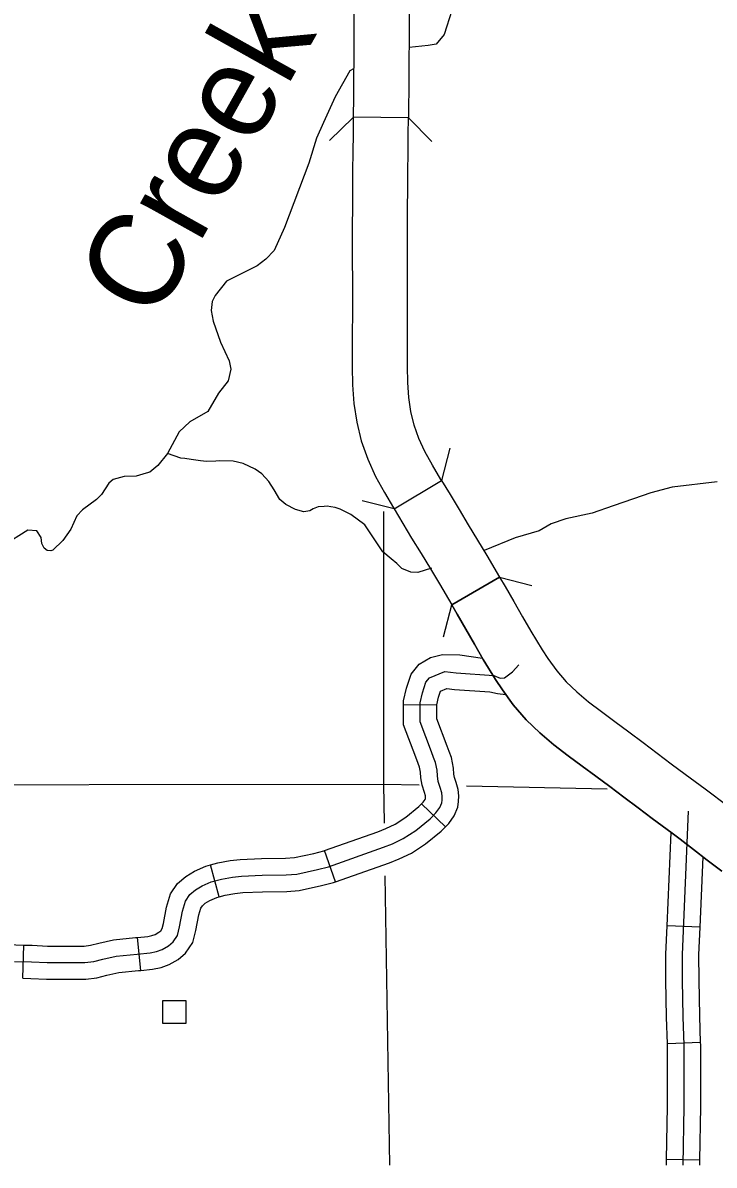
# Model space of a CAD drawing. Extents: x 1369885 to 1370219, y 379980 to 380218.
# Drawn here: x 1370041.37 to 1370053.81, y 380035.72 to 380056.29 of the extents above; entities that cross this region are included whole.
import ezdxf

# ---------------------------------------------------------------- set-up
doc = ezdxf.new("R2010")
doc.units = 0
for name, color, linetype in [('Level 10', 7, 'Continuous'), ('Level 32', 7, 'Continuous'), ('Level 35', 7, 'Continuous'), ('Level 37', 7, 'Continuous'), ('Level 5', 7, 'Continuous'), ('Level 56', 7, 'Continuous')]:
    doc.layers.add(name, color=color, linetype=linetype)

msp = doc.modelspace()

# ---------------------------------------------------------------- linework, layer by layer
at = {"layer": 'Level 10'}
for points in [[(1370047.332, 380056.674), (1370047.329, 380056.324), (1370047.326, 380055.979), (1370047.325, 380055.64), (1370047.321, 380055.305), (1370047.318, 380054.964), (1370047.316, 380054.593)], [(1370048.326, 380056.668), (1370048.323, 380056.316), (1370048.321, 380055.973), (1370048.319, 380055.632), (1370048.315, 380055.294), (1370048.31, 380054.582)], [(1370048.31, 380054.582), (1370047.316, 380054.593), (1370047.312, 380054.297), (1370047.308, 380053.964), (1370047.304, 380053.63), (1370047.301, 380053.298), (1370047.3, 380052.967), (1370047.298, 380052.639), (1370047.298, 380052.314), (1370047.299, 380051.993), (1370047.3, 380051.673), (1370047.3, 380051.353), (1370047.3, 380051.035), (1370047.299, 380050.721), (1370047.297, 380050.41), (1370047.298, 380050.096), (1370047.304, 380049.775), (1370047.327, 380049.441), (1370047.378, 380049.102), (1370047.459, 380048.763), (1370047.576, 380048.435), (1370047.718, 380048.126), (1370047.877, 380047.834), (1370048.043, 380047.559), (1370048.054, 380047.54), (1370048.906, 380048.053)], [(1370048.906, 380048.053), (1370048.895, 380048.072), (1370048.74, 380048.329), (1370048.607, 380048.573), (1370048.498, 380048.81), (1370048.414, 380049.047), (1370048.355, 380049.292), (1370048.316, 380049.548), (1370048.298, 380049.818), (1370048.293, 380050.107), (1370048.292, 380050.409), (1370048.293, 380050.717), (1370048.294, 380051.033), (1370048.294, 380051.353), (1370048.294, 380051.674), (1370048.294, 380051.995), (1370048.293, 380052.316), (1370048.293, 380052.637), (1370048.294, 380052.963), (1370048.296, 380053.29), (1370048.299, 380053.62), (1370048.302, 380053.952), (1370048.307, 380054.286), (1370048.31, 380054.582)], [(1370048.906, 380048.053), (1370049.058, 380047.8), (1370049.22, 380047.527), (1370049.386, 380047.253), (1370049.555, 380046.976), (1370049.722, 380046.701), (1370049.951, 380046.312)], [(1370048.054, 380047.54), (1370048.367, 380047.015), (1370048.537, 380046.737), (1370048.704, 380046.461), (1370048.868, 380046.19), (1370049.092, 380045.811)], [(1370049.951, 380046.312), (1370049.092, 380045.811), (1370049.188, 380045.646), (1370049.345, 380045.375), (1370049.499, 380045.105), (1370049.655, 380044.83), (1370049.879, 380044.465), (1370050.001, 380044.282), (1370050.197, 380044.008), (1370050.426, 380043.743), (1370050.674, 380043.504), (1370050.929, 380043.29), (1370051.185, 380043.093), (1370051.437, 380042.908), (1370051.684, 380042.726), (1370051.933, 380042.537), (1370052.186, 380042.346), (1370052.442, 380042.153), (1370052.696, 380041.965), (1370053.054, 380041.697), (1370053.199, 380041.59), (1370053.443, 380041.406), (1370053.688, 380041.215), (1370053.95, 380041.013)], [(1370053.95, 380041.013), (1370053.688, 380041.215), (1370053.443, 380041.406), (1370053.199, 380041.59), (1370053.054, 380041.697), (1370052.696, 380041.965), (1370052.442, 380042.153), (1370052.186, 380042.346), (1370051.933, 380042.537), (1370051.684, 380042.726), (1370051.437, 380042.908), (1370051.185, 380043.093), (1370050.929, 380043.29), (1370050.674, 380043.504), (1370050.426, 380043.743), (1370050.197, 380044.008), (1370050.001, 380044.282), (1370049.879, 380044.465), (1370049.655, 380044.83), (1370049.499, 380045.105), (1370049.345, 380045.375), (1370049.188, 380045.646), (1370049.092, 380045.811), (1370049.951, 380046.312)], [(1370049.951, 380046.312), (1370050.048, 380046.145), (1370050.207, 380045.871), (1370050.363, 380045.598), (1370050.512, 380045.336), (1370050.718, 380045.001), (1370050.82, 380044.847), (1370050.98, 380044.623), (1370051.149, 380044.427), (1370051.339, 380044.245), (1370051.553, 380044.065), (1370051.783, 380043.888), (1370052.027, 380043.709), (1370052.279, 380043.522), (1370052.533, 380043.331), (1370052.786, 380043.139), (1370053.037, 380042.95), (1370053.29, 380042.762), (1370053.648, 380042.495), (1370053.794, 380042.387), (1370054.048, 380042.195)], [(1370049.951, 380046.312), (1370050.048, 380046.145), (1370050.207, 380045.871), (1370050.363, 380045.598), (1370050.512, 380045.336), (1370050.718, 380045.001), (1370050.82, 380044.847), (1370050.98, 380044.623), (1370051.149, 380044.427), (1370051.339, 380044.245), (1370051.553, 380044.065), (1370051.783, 380043.888), (1370052.027, 380043.709), (1370052.279, 380043.522), (1370052.533, 380043.331), (1370052.786, 380043.139), (1370053.037, 380042.95), (1370053.29, 380042.762), (1370053.648, 380042.495), (1370053.794, 380042.387), (1370054.048, 380042.195)]]:
    msp.add_lwpolyline(points, dxfattribs=at)
at = {"layer": 'Level 32'}
for p, q in [((1370048.818, 380044.01), (1370048.222, 380044.007)), ((1370048.975, 380041.813), (1370048.547, 380042.229)), ((1370046.996, 380040.823), (1370046.798, 380041.385)), ((1370044.9, 380040.552), (1370044.745, 380041.128)), ((1370053.56, 380040.003), (1370052.964, 380040.029)), ((1370043.49, 380039.227), (1370043.433, 380039.821)), ((1370041.368, 380039.087), (1370041.385, 380039.684)), ((1370053.569, 380037.926), (1370052.973, 380037.906)), ((1370053.554, 380035.811), (1370052.957, 380035.821))]:
    msp.add_line(p, q, dxfattribs=at)
for points in [[(1370048.222, 380044.007), (1370048.221, 380044.08), (1370048.274, 380044.308), (1370048.358, 380044.563), (1370048.503, 380044.743), (1370048.704, 380044.862), (1370048.922, 380044.918), (1370049.234, 380044.91), (1370049.643, 380044.852)], [(1370041.218, 380039.39), (1370041.524, 380039.381), (1370041.803, 380039.368), (1370042.046, 380039.368), (1370042.261, 380039.368), (1370042.486, 380039.368), (1370042.644, 380039.386), (1370042.806, 380039.431), (1370043.049, 380039.485), (1370043.424, 380039.52), (1370043.658, 380039.543), (1370043.773, 380039.565), (1370043.874, 380039.603), (1370043.989, 380039.669), (1370044.072, 380039.741), (1370044.153, 380039.856), (1370044.189, 380040.009), (1370044.243, 380040.297), (1370044.297, 380040.477), (1370044.375, 380040.594), (1370044.476, 380040.679), (1370044.593, 380040.751), (1370044.76, 380040.823), (1370044.944, 380040.873), (1370045.142, 380040.909), (1370045.302, 380040.927), (1370045.675, 380040.942), (1370046.109, 380040.949), (1370046.298, 380040.963), (1370046.673, 380041.045), (1370046.87, 380041.095), (1370047.862, 380041.444), (1370048.023, 380041.508), (1370048.215, 380041.602), (1370048.44, 380041.748), (1370048.7, 380041.958), (1370048.805, 380042.066), (1370048.872, 380042.159), (1370048.91, 380042.247), (1370048.915, 380042.294), (1370048.918, 380042.358), (1370048.91, 380042.428), (1370048.883, 380042.522), (1370048.845, 380042.632), (1370048.831, 380042.729), (1370048.825, 380042.831), (1370048.799, 380042.974), (1370048.761, 380043.062), (1370048.726, 380043.167), (1370048.521, 380043.705), (1370048.52, 380044.047), (1370048.561, 380044.228), (1370048.625, 380044.418), (1370048.688, 380044.497), (1370048.963, 380044.612), (1370049.167, 380044.585), (1370049.844, 380044.54), (1370049.961, 380044.49), (1370050.036, 380044.495), (1370050.183, 380044.606), (1370050.298, 380044.733)], [(1370048.818, 380044.01), (1370048.818, 380044.013), (1370048.849, 380044.147), (1370048.885, 380044.256), (1370049.003, 380044.306), (1370049.137, 380044.288), (1370049.774, 380044.245), (1370049.913, 380044.216), (1370050.061, 380044.198)], [(1370048.547, 380042.229), (1370048.575, 380042.258), (1370048.611, 380042.307), (1370048.618, 380042.325), (1370048.619, 380042.346), (1370048.616, 380042.369), (1370048.598, 380042.433), (1370048.554, 380042.561), (1370048.534, 380042.698), (1370048.528, 380042.796), (1370048.511, 380042.887), (1370048.482, 380042.955), (1370048.445, 380043.067), (1370048.223, 380043.65), (1370048.222, 380044.007)], [(1370048.975, 380041.813), (1370049.034, 380041.874), (1370049.133, 380042.011), (1370049.2, 380042.168), (1370049.213, 380042.268), (1370049.218, 380042.37), (1370049.203, 380042.487), (1370049.168, 380042.61), (1370049.136, 380042.704), (1370049.128, 380042.76), (1370049.122, 380042.867), (1370049.086, 380043.061), (1370049.04, 380043.168), (1370049.007, 380043.267), (1370048.819, 380043.761), (1370048.818, 380044.01)], [(1370046.798, 380041.385), (1370047.757, 380041.723), (1370047.902, 380041.781), (1370048.068, 380041.862), (1370048.264, 380041.989), (1370048.498, 380042.179), (1370048.547, 380042.229)], [(1370053.254, 380035.719), (1370053.272, 380036.775), (1370053.272, 380037.879), (1370053.255, 380038.393), (1370053.243, 380039.052), (1370053.24, 380039.515), (1370053.351, 380042.096)], [(1370046.996, 380040.823), (1370047.967, 380041.165), (1370048.143, 380041.235), (1370048.362, 380041.341), (1370048.616, 380041.506), (1370048.901, 380041.737), (1370048.975, 380041.813)], [(1370052.964, 380040.029), (1370053.036, 380041.711)], [(1370044.745, 380041.128), (1370044.879, 380041.164), (1370045.099, 380041.204), (1370045.279, 380041.224), (1370045.666, 380041.241), (1370046.096, 380041.247), (1370046.255, 380041.259), (1370046.605, 380041.335), (1370046.784, 380041.38), (1370046.798, 380041.385)], [(1370053.56, 380040.003), (1370053.614, 380041.272)], [(1370043.433, 380039.821), (1370043.615, 380039.838), (1370043.691, 380039.853), (1370043.747, 380039.874), (1370043.815, 380039.914), (1370043.849, 380039.942), (1370043.876, 380039.98), (1370043.897, 380040.07), (1370043.952, 380040.367), (1370044.024, 380040.606), (1370044.151, 380040.795), (1370044.301, 380040.921), (1370044.455, 380041.016), (1370044.661, 380041.106), (1370044.745, 380041.128)], [(1370044.9, 380040.552), (1370045.01, 380040.581), (1370045.186, 380040.613), (1370045.325, 380040.629), (1370045.684, 380040.644), (1370046.122, 380040.651), (1370046.341, 380040.667), (1370046.742, 380040.754), (1370046.957, 380040.809), (1370046.996, 380040.823)], [(1370043.49, 380039.227), (1370043.701, 380039.247), (1370043.855, 380039.277), (1370044.001, 380039.333), (1370044.162, 380039.424), (1370044.294, 380039.539), (1370044.43, 380039.731), (1370044.481, 380039.947), (1370044.533, 380040.226), (1370044.569, 380040.348), (1370044.6, 380040.393), (1370044.652, 380040.437), (1370044.732, 380040.486), (1370044.858, 380040.541), (1370044.9, 380040.552)], [(1370039.391, 380040.04), (1370039.651, 380039.972), (1370040.164, 380039.843), (1370040.61, 380039.752), (1370040.806, 380039.728), (1370040.997, 380039.714), (1370041.239, 380039.688), (1370041.385, 380039.684)], [(1370052.973, 380037.906), (1370052.957, 380038.385), (1370052.945, 380039.049), (1370052.942, 380039.52), (1370052.964, 380040.029)], [(1370053.569, 380037.926), (1370053.553, 380038.4), (1370053.541, 380039.056), (1370053.539, 380039.509), (1370053.56, 380040.003)], [(1370041.385, 380039.684), (1370041.536, 380039.679), (1370041.81, 380039.666), (1370042.046, 380039.666), (1370042.261, 380039.666), (1370042.469, 380039.666), (1370042.587, 380039.679), (1370042.733, 380039.72), (1370043.002, 380039.78), (1370043.396, 380039.817), (1370043.433, 380039.821)], [(1370041.368, 380039.087), (1370041.512, 380039.083), (1370041.796, 380039.069), (1370042.046, 380039.069), (1370042.261, 380039.069), (1370042.503, 380039.069), (1370042.701, 380039.092), (1370042.878, 380039.141), (1370043.095, 380039.189), (1370043.452, 380039.223), (1370043.49, 380039.227)], [(1370052.957, 380035.821), (1370052.974, 380036.777), (1370052.974, 380037.874), (1370052.973, 380037.906)], [(1370053.554, 380035.811), (1370053.571, 380036.772), (1370053.571, 380037.884), (1370053.569, 380037.926)], [(1370052.956, 380035.719), (1370052.957, 380035.821)], [(1370053.552, 380035.719), (1370053.554, 380035.811)]]:
    msp.add_lwpolyline(points, dxfattribs=at)
at = {"layer": 'Level 35'}
for points in [[(1370049.089, 380056.516), (1370048.954, 380056.084), (1370048.81, 380055.913), (1370048.666, 380055.886), (1370048.32, 380055.852)], [(1370047.323, 380055.468), (1370047.256, 380055.429), (1370046.989, 380054.963), (1370046.779, 380054.498), (1370046.651, 380054.216), (1370046.518, 380053.769), (1370046.075, 380052.61), (1370045.89, 380052.194), (1370045.743, 380052.038), (1370045.584, 380051.918), (1370045.036, 380051.642), (1370044.83, 380051.385), (1370044.777, 380051.275), (1370044.758, 380051.115), (1370044.796, 380050.921), (1370044.923, 380050.542), (1370045.08, 380050.204), (1370045.112, 380050.054), (1370045.063, 380049.849), (1370044.887, 380049.625), (1370044.695, 380049.292), (1370044.375, 380049.107), (1370044.181, 380048.925), (1370043.971, 380048.536), (1370043.795, 380048.32), (1370043.651, 380048.204), (1370043.588, 380048.182), (1370043.407, 380048.129), (1370043.193, 380048.122), (1370042.996, 380048.072), (1370042.918, 380048.002), (1370042.786, 380047.799), (1370042.693, 380047.708), (1370042.441, 380047.521), (1370042.34, 380047.415), (1370042.233, 380047.176), (1370042.088, 380046.968), (1370041.91, 380046.796), (1370041.871, 380046.786), (1370041.807, 380046.789), (1370041.75, 380046.831), (1370041.708, 380046.917), (1370041.697, 380047.024), (1370041.618, 380047.142), (1370041.455, 380047.156), (1370041.018, 380046.88)], [(1370046.534, 380047.505), (1370046.427, 380047.487), (1370046.278, 380047.528), (1370046.102, 380047.622), (1370045.994, 380047.712), (1370045.89, 380047.882), (1370045.794, 380048.032), (1370045.671, 380048.173), (1370045.548, 380048.255), (1370045.336, 380048.355), (1370045.151, 380048.401), (1370044.904, 380048.404), (1370044.84, 380048.4), (1370044.674, 380048.395), (1370044.566, 380048.406), (1370044.398, 380048.429), (1370044.285, 380048.447), (1370044.209, 380048.454), (1370043.971, 380048.536)], [(1370053.869, 380048.028), (1370053.059, 380047.933), (1370052.671, 380047.828), (1370052.359, 380047.724), (1370051.996, 380047.593), (1370051.617, 380047.461), (1370051.14, 380047.361), (1370050.879, 380047.271), (1370050.663, 380047.145), (1370050.231, 380047.019), (1370049.67, 380046.789)], [(1370048.724, 380046.47), (1370048.478, 380046.394), (1370048.354, 380046.4), (1370048.189, 380046.469), (1370048.099, 380046.559), (1370048, 380046.64), (1370047.848, 380046.765), (1370047.693, 380047), (1370047.524, 380047.25), (1370047.274, 380047.44), (1370047.082, 380047.538), (1370046.993, 380047.567), (1370046.911, 380047.578), (1370046.843, 380047.591), (1370046.79, 380047.584), (1370046.684, 380047.58), (1370046.595, 380047.54), (1370046.534, 380047.505)]]:
    msp.add_lwpolyline(points, dxfattribs=at)
at = {"layer": 'Level 37'}
for points in [[(1370046.89, 380054.174), (1370047.316, 380054.592)], [(1370048.31, 380054.583), (1370048.728, 380054.158)], [(1370049.052, 380048.631), (1370048.907, 380048.052)], [(1370048.053, 380047.541), (1370047.475, 380047.687)], [(1370049.951, 380046.312), (1370050.528, 380046.16)], [(1370048.94, 380045.234), (1370049.092, 380045.811)]]:
    msp.add_lwpolyline(points, dxfattribs=at)
at = {"layer": 'Level 5'}
for points in [[(1370047.861, 380047.491), (1370047.86, 380042.58)], [(1370026.649, 380042.559), (1370047.86, 380042.58)], [(1370047.86, 380042.58), (1370048.504, 380042.567)], [(1370047.86, 380042.58), (1370047.871, 380041.877)], [(1370049.356, 380042.549), (1370051.884, 380042.497)], [(1370047.886, 380040.932), (1370047.969, 380035.719)]]:
    msp.add_lwpolyline(points, dxfattribs=at)
at = {"layer": 'Level 56'}
msp.add_lwpolyline([(1370043.886, 380038.27), (1370043.886, 380038.684), (1370044.301, 380038.684), (1370044.301, 380038.27)], close=True, dxfattribs=at)

# ---------------------------------------------------------------- texts
at = {"layer": 'Level 35'}
msp.add_text('Creek', height=1.6802, rotation=60.7588, dxfattribs=at).set_placement((1370043.737, 380050.869))

doc.saveas('drawing.dxf')
